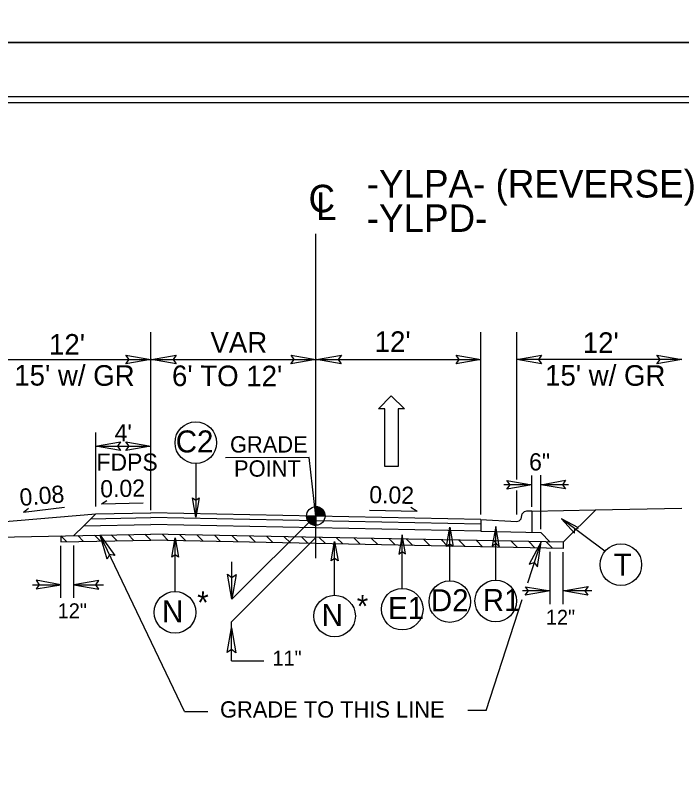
# Model space of a CAD drawing. Extents: x 573813 to 575363, y -54752 to -53123.
# Drawn here: x 574829.6 to 574884.7, y -53623.9 to -53560.8 of the extents above; entities that cross this region are included whole.
import ezdxf

# ---------------------------------------------------------------- set-up
doc = ezdxf.new("R2010")
doc.units = 0
for name, color, linetype in [('Old_Level_1', 7, 'Continuous'), ('Old_Level_11', 7, 'Continuous'), ('Old_Level_2', 7, 'Continuous'), ('Old_Level_3', 7, 'Continuous'), ('Prop Lane Arrow CELL', 7, 'Continuous'), ('Prop Pavement Schedule Description CELL', 7, 'Continuous'), ('Prop XS Finish Grade CurbGutter', 7, 'Continuous'), ('Prop XS Subgrade CurbGutter', 7, 'Continuous'), ('Sheet Cutting Line CELL', 7, 'Continuous'), ('Sheet Plot Border Inside CELL', 7, 'Continuous'), ('Sheet Plot Border Outside CELL', 7, 'Continuous'), ('Sheet Typical CELL', 7, 'Continuous'), ('Typical Grade Point Symbol CELL', 7, 'Continuous'), ('Typical ID Circle CELL', 7, 'Continuous'), ('Typical Terminator CELL', 7, 'Continuous'), ('Typical Text ID Circle CELL', 7, 'Continuous')]:
    doc.layers.add(name, color=color, linetype=linetype)

msp = doc.modelspace()

# ---------------------------------------------------------------- linework, layer by layer
at = {"layer": 'Old_Level_1'}
for p, q in [((574877.577, -53601.709), (574884.732, -53601.566)), ((574827.202, -53602.797), (574836.298, -53602.039)), ((574836.298, -53602.039), (574835.312, -53603.026)), ((574836.298, -53602.039), (574840.846, -53601.948)), ((574868.133, -53602.494), (574840.846, -53601.948)), ((574872.334, -53601.814), (574877.577, -53601.709)), ((574877.628, -53601.708), (574874.944, -53604.391)), ((574835.312, -53603.026), (574840.846, -53602.915)), ((574835.892, -53602.446), (574840.846, -53602.346)), ((574868.125, -53602.892), (574840.846, -53602.346)), ((574868.133, -53603.483), (574840.846, -53602.908)), ((574835.312, -53603.026), (574834.501, -53603.836)), ((574873.079, -53603.582), (574873.867, -53604.37)), ((574819.123, -53604.144), (574840.846, -53603.709)), ((574833.424, -53603.858), (574833.424, -53604.358)), ((574833.424, -53603.858), (574833.914, -53604.348)), ((574833.424, -53604.358), (574840.856, -53604.209)), ((574834.81, -53603.83), (574835.3, -53604.32)), ((574836.196, -53603.802), (574836.687, -53604.292)), ((574837.583, -53603.774), (574838.073, -53604.265)), ((574838.969, -53603.747), (574839.46, -53604.237)), ((574840.356, -53603.719), (574840.846, -53604.21)), ((574874.944, -53604.892), (574840.836, -53604.209)), ((574874.944, -53604.391), (574840.846, -53603.709)), ((574841.779, -53603.728), (574842.289, -53604.238)), ((574843.222, -53603.757), (574843.733, -53604.267)), ((574844.665, -53603.786), (574845.176, -53604.296)), ((574846.108, -53603.814), (574846.619, -53604.325)), ((574847.551, -53603.843), (574848.062, -53604.354)), ((574848.994, -53603.872), (574849.505, -53604.383)), ((574850.437, -53603.901), (574850.948, -53604.412)), ((574851.881, -53603.93), (574852.391, -53604.44)), ((574853.324, -53603.959), (574853.834, -53604.469)), ((574854.767, -53603.988), (574855.277, -53604.498)), ((574856.21, -53604.017), (574856.72, -53604.527)), ((574857.653, -53604.045), (574858.163, -53604.556)), ((574859.096, -53604.074), (574859.606, -53604.585)), ((574860.539, -53604.103), (574861.05, -53604.614)), ((574861.982, -53604.132), (574862.493, -53604.643)), ((574863.425, -53604.161), (574863.936, -53604.671)), ((574864.868, -53604.19), (574865.379, -53604.7)), ((574866.311, -53604.219), (574866.822, -53604.729)), ((574867.755, -53604.248), (574868.265, -53604.758)), ((574869.198, -53604.277), (574869.708, -53604.787)), ((574870.641, -53604.305), (574871.151, -53604.816)), ((574872.084, -53604.334), (574872.594, -53604.845)), ((574873.527, -53604.363), (574874.037, -53604.873)), ((574874.944, -53604.391), (574874.944, -53604.892))]:
    msp.add_line(p, q, dxfattribs=at)
at = {"layer": 'Old_Level_11'}
for p, q in [((574840.846, -53601.731), (574840.846, -53587.033)), ((574868.133, -53602.102), (574868.133, -53587.032)), ((574871.088, -53599.2), (574871.088, -53587.032)), ((574827.202, -53589.288), (574840.846, -53589.289)), ((574840.846, -53589.289), (574854.489, -53589.289)), ((574854.489, -53589.289), (574868.133, -53589.288)), ((574884.731, -53589.288), (574871.088, -53589.288)), ((574836.298, -53601.434), (574836.298, -53595.32)), ((574836.298, -53596.453), (574840.846, -53596.453)), ((574853.925, -53597.389), (574847.013, -53597.411)), ((574854.489, -53602.221), (574853.925, -53597.389)), ((574872.334, -53601.47), (574872.334, -53598.86)), ((574873.079, -53603.303), (574873.079, -53598.839)), ((574872.334, -53599.634), (574870.039, -53599.637)), ((574875.373, -53599.63), (574873.079, -53599.633)), ((574871.088, -53602.102), (574871.088, -53600.111)), ((574854.425, -53602.221), (574847.555, -53609.092)), ((574843.63, -53618.386), (574836.671, -53603.793)), ((574854.489, -53603.982), (574847.517, -53610.954)), ((574833.423, -53608.981), (574833.423, -53604.688)), ((574834.501, -53608.981), (574834.501, -53604.663)), ((574871.997, -53607.749), (574873.103, -53604.355)), ((574873.853, -53609.494), (574873.853, -53605.176)), ((574874.93, -53609.494), (574874.93, -53605.2)), ((574847.555, -53609.092), (574847.555, -53606.016)), ((574831.065, -53607.895), (574833.423, -53607.898)), ((574834.501, -53607.9), (574836.933, -53607.903)), ((574873.853, -53608.412), (574871.558, -53608.415)), ((574877.289, -53608.407), (574874.93, -53608.411)), ((574868.562, -53618.298), (574871.551, -53609.119)), ((574847.517, -53614.189), (574847.517, -53610.954)), ((574847.517, -53614.189), (574850.181, -53614.189)), ((574843.63, -53618.386), (574845.576, -53618.386)), ((574868.562, -53618.298), (574867.049, -53618.298))]:
    msp.add_line(p, q, dxfattribs=at)
for points in [[(574838.799, -53588.936), (574840.846, -53589.289), (574838.788, -53589.652), (574839.049, -53589.289)], [(574842.946, -53589.641), (574840.899, -53589.289), (574842.957, -53588.925), (574842.696, -53589.289)], [(574852.443, -53588.936), (574854.489, -53589.289), (574852.431, -53589.652), (574852.693, -53589.289)], [(574856.59, -53589.641), (574854.543, -53589.289), (574856.601, -53588.925), (574856.34, -53589.288)], [(574866.087, -53588.936), (574868.133, -53589.288), (574866.075, -53589.652), (574866.337, -53589.289)], [(574873.134, -53589.641), (574871.088, -53589.288), (574873.145, -53588.925), (574872.884, -53589.288)], [(574882.685, -53588.936), (574884.731, -53589.288), (574882.673, -53589.652), (574882.935, -53589.288)], [(574838.336, -53596.804), (574836.289, -53596.451), (574838.347, -53596.088), (574838.086, -53596.451)], [(574838.8, -53596.1), (574840.846, -53596.453), (574838.788, -53596.816), (574839.05, -53596.453)], [(574870.287, -53599.282), (574872.334, -53599.634), (574870.276, -53599.998), (574870.537, -53599.634)], [(574875.125, -53599.986), (574873.079, -53599.633), (574875.137, -53599.269), (574874.875, -53599.633)], [(574837.233, -53605.792), (574836.671, -53603.793), (574837.885, -53605.494), (574837.444, -53605.414)], [(574872.804, -53606.41), (574873.103, -53604.355), (574872.119, -53606.199), (574872.546, -53606.063)], [(574847.907, -53607.045), (574847.555, -53609.092), (574847.191, -53607.034), (574847.555, -53607.295)], [(574831.377, -53608.251), (574833.423, -53607.898), (574831.366, -53607.534), (574831.627, -53607.898)], [(574836.548, -53607.547), (574834.501, -53607.9), (574836.559, -53608.263), (574836.298, -53607.9)], [(574871.806, -53608.06), (574873.853, -53608.412), (574871.795, -53608.776), (574872.056, -53608.412)], [(574876.977, -53608.763), (574874.93, -53608.411), (574876.988, -53608.047), (574876.727, -53608.411)], [(574847.165, -53613.514), (574847.517, -53611.468), (574847.881, -53613.525), (574847.517, -53613.264)]]:
    msp.add_lwpolyline(points, close=True, dxfattribs=at)
at = {"layer": 'Old_Level_2'}
for p, q in [((574854.489, -53580.565), (574854.489, -53578.897)), ((574854.489, -53605.712), (574854.489, -53580.565)), ((574836.78, -53601.203), (574837.211, -53600.943)), ((574830.324, -53601.905), (574833.731, -53601.482)), ((574830.324, -53601.905), (574830.755, -53601.579)), ((574836.78, -53601.203), (574840.213, -53601.134)), ((574862.871, -53601.837), (574862.34, -53601.516)), ((574862.871, -53601.837), (574858.919, -53601.758))]:
    msp.add_line(p, q, dxfattribs=at)
at = {"layer": 'Prop Lane Arrow CELL'}
for p, q in [((574859.669, -53593.361), (574860.727, -53592.286)), ((574860.727, -53592.286), (574861.818, -53593.361)), ((574860.181, -53593.361), (574859.669, -53593.361)), ((574860.181, -53598.136), (574860.181, -53593.361)), ((574861.818, -53593.361), (574861.307, -53593.361)), ((574861.307, -53593.361), (574861.307, -53598.136)), ((574861.307, -53598.136), (574860.181, -53598.136))]:
    msp.add_line(p, q, dxfattribs=at)
at = {"layer": 'Prop XS Finish Grade CurbGutter'}
for p, q in [((574871.448, -53602.463), (574871.545, -53602.033)), ((574871.545, -53602.033), (574871.695, -53601.871)), ((574871.908, -53601.831), (574871.695, -53601.871)), ((574872.334, -53601.814), (574871.908, -53601.831)), ((574868.094, -53602.495), (574871.088, -53602.674)), ((574871.088, -53602.674), (574871.299, -53602.626)), ((574871.299, -53602.626), (574871.448, -53602.463))]:
    msp.add_line(p, q, dxfattribs=at)
at = {"layer": 'Prop XS Subgrade CurbGutter'}
for p, q in [((574872.334, -53601.814), (574872.334, -53603.567)), ((574868.133, -53602.494), (574868.133, -53603.483)), ((574868.133, -53603.483), (574873.079, -53603.582))]:
    msp.add_line(p, q, dxfattribs=at)
at = {"layer": 'Sheet Cutting Line CELL'}
for p, q in [((575006.712, -53563.07), (574669.731, -53563.07)), ((574669.731, -53563.07), (575006.712, -53563.07))]:
    msp.add_line(p, q, dxfattribs=at)
at = {"layer": 'Sheet Plot Border Inside CELL'}
msp.add_lwpolyline([(575005.811, -53567.563), (574672.332, -53567.563), (574672.332, -53778.696), (575005.811, -53778.696)], close=True, dxfattribs=at)
at = {"layer": 'Sheet Plot Border Outside CELL'}
for p, q in [((574669.731, -53563.07), (575006.712, -53563.07)), ((575006.712, -53563.07), (574669.731, -53563.07))]:
    msp.add_line(p, q, dxfattribs=at)
for points in [[(575006.712, -53342.952), (574669.731, -53342.952), (574669.731, -53563.07), (575006.712, -53563.07)], [(575006.712, -53563.07), (574669.731, -53563.07), (574669.731, -53783.189), (575006.712, -53783.189)]]:
    msp.add_lwpolyline(points, close=True, dxfattribs=at)
at = {"layer": 'Sheet Typical CELL'}
msp.add_lwpolyline([(575003.31, -53568.073), (574703.149, -53568.073), (574703.149, -53778.186), (575003.31, -53778.186)], close=True, dxfattribs=at)
at = {"layer": 'Typical Grade Point Symbol CELL'}
for p, q in [((574854.489, -53602.221), (574854.489, -53601.458)), ((574853.726, -53602.221), (574854.489, -53602.221)), ((574854.487, -53602.985), (574854.489, -53602.221)), ((574854.489, -53602.221), (574854.487, -53602.985)), ((574855.252, -53602.221), (574854.489, -53602.221))]:
    msp.add_line(p, q, dxfattribs=at)
for points in [[(574854.496, -53601.458), (574854.496, -53601.458), (574854.496, -53602.221)], [(574854.511, -53601.458), (574854.511, -53602.221)], [(574854.527, -53601.46), (574854.527, -53602.221)], [(574854.542, -53601.46), (574854.542, -53602.221)], [(574854.557, -53601.461), (574854.557, -53602.221)], [(574854.572, -53601.463), (574854.572, -53602.221)], [(574854.588, -53601.465), (574854.588, -53602.221)], [(574854.603, -53601.466), (574854.603, -53602.221)], [(574854.618, -53601.468), (574854.618, -53602.221)], [(574854.633, -53601.472), (574854.633, -53602.221)], [(574854.649, -53601.475), (574854.649, -53602.221)], [(574854.664, -53601.478), (574854.664, -53602.221)], [(574854.679, -53601.482), (574854.679, -53602.221)], [(574854.694, -53601.487), (574854.694, -53602.221)], [(574854.71, -53601.49), (574854.71, -53602.221)], [(574854.725, -53601.495), (574854.725, -53602.221)], [(574854.74, -53601.5), (574854.74, -53602.221)], [(574854.755, -53601.505), (574854.755, -53602.221)], [(574854.771, -53601.512), (574854.771, -53602.221)], [(574854.786, -53601.519), (574854.786, -53602.221)], [(574854.801, -53601.526), (574854.801, -53602.221)], [(574854.817, -53601.533), (574854.817, -53602.221)], [(574854.832, -53601.539), (574854.832, -53602.221)], [(574854.847, -53601.548), (574854.847, -53602.221)], [(574854.862, -53601.556), (574854.862, -53602.221)], [(574854.878, -53601.565), (574854.878, -53602.221)], [(574854.893, -53601.573), (574854.893, -53602.221)], [(574854.908, -53601.584), (574854.908, -53602.221)], [(574854.923, -53601.594), (574854.923, -53602.221)], [(574854.939, -53601.606), (574854.939, -53602.221)], [(574854.954, -53601.616), (574854.954, -53602.221)], [(574854.969, -53601.628), (574854.969, -53602.221)], [(574854.985, -53601.641), (574854.985, -53602.221)], [(574855, -53601.655), (574855, -53602.221)], [(574855.015, -53601.668), (574855.015, -53602.221)], [(574855.03, -53601.684), (574855.03, -53602.221)], [(574853.729, -53602.221), (574853.729, -53602.304)], [(574853.744, -53602.221), (574853.744, -53602.394)], [(574853.76, -53602.221), (574853.76, -53602.449)], [(574853.775, -53602.221), (574853.775, -53602.494)], [(574853.79, -53602.221), (574853.79, -53602.53)], [(574853.806, -53602.221), (574853.806, -53602.562)], [(574853.821, -53602.221), (574853.821, -53602.591)], [(574853.836, -53602.221), (574853.836, -53602.618)], [(574853.851, -53602.221), (574853.851, -53602.642)], [(574853.867, -53602.221), (574853.867, -53602.664)], [(574853.882, -53602.221), (574853.882, -53602.684)], [(574853.897, -53602.221), (574853.897, -53602.703)], [(574853.912, -53602.221), (574853.912, -53602.722)], [(574853.928, -53602.221), (574853.928, -53602.739)], [(574853.943, -53602.221), (574853.943, -53602.756)], [(574853.958, -53602.221), (574853.958, -53602.771)], [(574853.974, -53602.221), (574853.974, -53602.785)], [(574853.989, -53602.221), (574853.989, -53602.798)], [(574854.004, -53602.221), (574854.004, -53602.812)], [(574854.019, -53602.221), (574854.019, -53602.823)], [(574854.035, -53602.221), (574854.035, -53602.835)], [(574854.05, -53602.221), (574854.05, -53602.846)], [(574854.065, -53602.221), (574854.065, -53602.856)], [(574854.08, -53602.221), (574854.08, -53602.866)], [(574854.096, -53602.221), (574854.096, -53602.876)], [(574854.111, -53602.221), (574854.111, -53602.885)], [(574854.126, -53602.221), (574854.126, -53602.893)], [(574854.141, -53602.221), (574854.141, -53602.902)], [(574854.157, -53602.221), (574854.157, -53602.908)], [(574854.172, -53602.221), (574854.172, -53602.915)], [(574854.187, -53602.221), (574854.187, -53602.922)], [(574854.202, -53602.221), (574854.202, -53602.929)], [(574854.218, -53602.221), (574854.218, -53602.935)], [(574854.233, -53602.221), (574854.233, -53602.941)], [(574854.248, -53602.221), (574854.248, -53602.946)], [(574854.264, -53602.221), (574854.264, -53602.951)], [(574854.279, -53602.221), (574854.279, -53602.954)], [(574854.294, -53602.221), (574854.294, -53602.959)], [(574854.309, -53602.221), (574854.309, -53602.963)], [(574854.325, -53602.221), (574854.325, -53602.966)], [(574854.34, -53602.221), (574854.34, -53602.969)], [(574854.355, -53602.221), (574854.355, -53602.973)], [(574854.37, -53602.221), (574854.37, -53602.974)], [(574854.386, -53602.221), (574854.386, -53602.978)], [(574854.401, -53602.221), (574854.401, -53602.98)], [(574854.416, -53602.221), (574854.416, -53602.981)], [(574854.432, -53602.221), (574854.432, -53602.983)], [(574854.447, -53602.221), (574854.447, -53602.983)], [(574854.462, -53602.221), (574854.462, -53602.985)], [(574854.477, -53602.221), (574854.477, -53602.985), (574854.477, -53602.985)], [(574855.046, -53601.699), (574855.046, -53602.221)], [(574855.061, -53601.716), (574855.061, -53602.221)], [(574855.076, -53601.734), (574855.076, -53602.221)], [(574855.091, -53601.753), (574855.091, -53602.221)], [(574855.107, -53601.773), (574855.107, -53602.221)], [(574855.122, -53601.796), (574855.122, -53602.221)], [(574855.137, -53601.819), (574855.137, -53602.221)], [(574855.152, -53601.845), (574855.152, -53602.221)], [(574855.168, -53601.872), (574855.168, -53602.221)], [(574855.183, -53601.904), (574855.183, -53602.221)], [(574855.198, -53601.94), (574855.198, -53602.221)], [(574855.213, -53601.982), (574855.213, -53602.221)], [(574855.229, -53602.035), (574855.229, -53602.221)], [(574855.244, -53602.113), (574855.244, -53602.221)]]:
    msp.add_lwpolyline(points, dxfattribs=at)
msp.add_circle((574854.488, -53602.221), 0.763, dxfattribs=at)
for start, end in [(359.99048, 89.99048), (179.99048, 269.99048)]:
    msp.add_arc((574854.488, -53602.221), 0.763, start, end, dxfattribs=at)
at = {"layer": 'Typical ID Circle CELL'}
for p, q in [((574844.568, -53597.874), (574844.568, -53602.313)), ((574878.369, -53605.136), (574874.783, -53602.44)), ((574865.562, -53607.579), (574865.562, -53603.14)), ((574869.359, -53607.527), (574869.359, -53603.089)), ((574842.852, -53608.466), (574842.852, -53604.027)), ((574861.632, -53608.204), (574861.632, -53603.765)), ((574856.043, -53608.77), (574856.043, -53604.332))]:
    msp.add_line(p, q, dxfattribs=at)
for centre in [(574844.568, -53596.157), (574879.7, -53606.24), (574865.562, -53609.296), (574869.359, -53609.244), (574842.852, -53610.183), (574861.632, -53609.921), (574856.043, -53610.487)]:
    msp.add_circle(centre, 1.718, dxfattribs=at)
at = {"layer": 'Typical Terminator CELL'}
for points in [[(574844.842, -53600.723), (574844.568, -53602.313), (574844.286, -53600.714), (574844.568, -53600.917)], [(574876.205, -53603.204), (574874.783, -53602.44), (574875.869, -53603.648), (574875.883, -53603.3)], [(574865.288, -53604.73), (574865.562, -53603.14), (574865.845, -53604.739), (574865.562, -53604.536)], [(574869.633, -53604.679), (574869.359, -53603.089), (574869.076, -53604.688), (574869.359, -53604.485)], [(574842.578, -53605.618), (574842.852, -53604.027), (574843.135, -53605.626), (574842.852, -53605.423)], [(574861.906, -53605.355), (574861.632, -53603.765), (574861.349, -53605.364), (574861.632, -53605.161)], [(574855.769, -53605.922), (574856.043, -53604.332), (574856.326, -53605.931), (574856.043, -53605.727)]]:
    msp.add_lwpolyline(points, close=True, dxfattribs=at)

# ---------------------------------------------------------------- texts
at = {"layer": 'Old_Level_1'}
for s, height, rotation, p in [('FDPS', 1.4212, 359.99995, (574836.356, -53598.474)), ('*', 1.819, 0, (574844.684, -53610.274)), ('*', 1.819, 0, (574857.875, -53610.578))]:
    msp.add_text(s, height=height, rotation=rotation, dxfattribs=at).set_placement(p)
at = {"layer": 'Old_Level_11'}
for s, height, p in [("12'", 1.7055, (574876.555, -53588.74)), ('GRADE TO THIS LINE', 1.35016, (574846.571, -53618.884))]:
    msp.add_text(s, height=height, rotation=359.99996, dxfattribs=at).set_placement(p)
at = {"layer": 'Old_Level_2'}
for s, rotation, p in [('C', 359.99996, (574853.884, -53577.112)), ('L', 359.94686, (574854.505, -53577.749))]:
    msp.add_text(s, height=2.274, rotation=rotation, dxfattribs=at).set_placement(p)
at = {"layer": 'Old_Level_3'}
for s, height, rotation, p in [('-YLPA- (REVERSE)', 2.27395, 0, (574858.697, -53575.891)), ('-YLPD-', 2.2739, 0, (574858.697, -53578.733)), ("12'", 1.7055, 359.83288, (574832.439, -53588.879)), ('VAR', 1.7055, 359.83288, (574845.78, -53588.713)), ("12'", 1.7055, 359.83288, (574859.35, -53588.655)), ("15' w/ GR", 1.7055, 359.83288, (574829.567, -53591.433)), ("15' w/ GR", 1.7055, 359.83288, (574873.437, -53591.433)), ("6' TO 12'", 1.7055, 359.83288, (574842.6, -53591.475)), ("4'", 1.4212, 359.83288, (574837.859, -53596.049)), ('GRADE', 1.3502, 0.00004, (574847.396, -53596.971)), ('6"', 1.4212, 359.83288, (574872.114, -53598.45)), ('POINT', 1.3502, 0.00004, (574847.729, -53598.966)), ('0.02 ', 1.4212, 1.14574, (574836.686, -53600.684)), ('0.08', 1.4212, 4.8822, (574830.065, -53601.397)), ('0.02', 1.4212, 358.85426, (574858.896, -53601.153))]:
    msp.add_text(s, height=height, rotation=rotation, dxfattribs=at).set_placement(p)
at = {"layer": 'Prop Pavement Schedule Description CELL'}
for s, height, p in [('C2', 1.8192, (574842.912, -53596.965)), ('T', 1.819, (574879.102, -53607.149)), ('D2', 1.8192, (574864.001, -53610.094)), ('N', 1.819, (574841.779, -53611.001)), ('E1', 1.8192, (574860.46, -53610.728)), ('N', 1.819, (574854.97, -53611.305))]:
    msp.add_text(s, height=height, rotation=360, dxfattribs=at).set_placement(p)
msp.add_text('R1', height=1.8192, dxfattribs=at).set_placement((574868.286, -53610.074))
at = {"layer": 'Typical Text ID Circle CELL'}
for s, p in [('12"', (574833.156, -53610.668)), ('12"', (574873.504, -53611.204)), ('11"', (574850.904, -53614.582))]:
    msp.add_text(s, height=1.2298, dxfattribs=at).set_placement(p)

doc.saveas('drawing.dxf')
